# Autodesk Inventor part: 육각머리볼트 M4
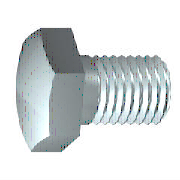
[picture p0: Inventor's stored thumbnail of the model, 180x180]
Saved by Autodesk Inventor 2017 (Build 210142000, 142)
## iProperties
Created: 2012-02
Part Number: 육각머리볼트 M4
Material: 스테인리스강
Description: 6각 머리 나사
Document SubType Name: Modeling
Standard: ISO 4017
Designer: mduedu
Standard Revision: Third edition 1999-08-15
Standards Organization: ISO
Language: ko-KR
Size Designation: M4 x 10
Categories: <MemberInstance><Categories><Category DisplayName="조임쇠" InternalName="e4da775c-781d-43d5-af7c-5136215cf5a6" Mnemonic="FSTN"><Category DisplayName="볼트" InternalN
Density: 8.08 g/cm^3
Appearance: 반광택
IsCustomPart: 0
Author: mduedu
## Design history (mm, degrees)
sketch "스케치1"
  geometry: L1 (0, 3.015)-(0, 2); L2 (1.75, 2)-(10, 2); L3 (10, 2)-(10, 0); L4 (10, 0)-(-0.4, 0); L5 (-2.48, 0)-(12.08, 0) reference; L6 (-0.4, 0)-(-0.4, 3.015); L7 (-0.4, 3.015)-(0, 3.015); L8 (1.75, 2)-(1.32, 2); L9 (1.32, 2)-(0, 2); L10 (0, -0.603)-(0, 3.618) reference
  constraints: 16 end point, 2 collinear, 2 perpendicular, 1 parallel
  dimensions: "d0" = 10 distance between parallel lines of L3 L1 (= NLG); "d1" = 8.25 distance from line of L2.start L3 (= GEL); "d2" = 4 diameter of L2 L4 (= GD); "d9" = 0.4001 distance between parallel lines of L6 L1 (computed from SD); "d10" = 6.03 diameter of L7 L4 (= SD2); "d13" = 0.42952 distance of L2.start L8.end (computed from GAL); "d14" = 4 diameter of L9 L4 (= BDM)
revolve "본체" sketch "스케치1" stored, may be unused: angle "d12" = 90 deg
sketch "스케치2"
  geometry: L1 (0, 4.041)-(3.5, 2.021); L2 (3.5, 2.021)-(3.5, -2.021); L3 (3.5, -2.021)-(0, -4.041); L4 (0, -4.041)-(-3.5, -2.021); L5 (-3.5, -2.021)-(-3.5, 2.021); L6 (-3.5, 2.021)-(0, 4.041); 2 further points
  constraints: 12 end point, 1 coincident, 1 vertical, 11 other
  dimensions: "d11" = 7 distance between parallel lines of L5 L2 (= SW)
extrude "머리" join sketch "스케치2" distance "d3" = 2.4 (= KOH - SD); taper "d4" = 0 deg
sketch "스케치4"
  geometry: L1 (-2.8, 3.5)-(-2.8, 4.041); L2 (-2.8, 4.041)-(-2.487, 4.041); L3 (-2.487, 4.041)-(-2.8, 3.5); L4 (-3.28, 0)-(0.08, 0) reference; L5 (-0.4, 4.041)-(-2.8, 4.041) reference; L6 (-2.8, 2.021)-(-2.8, 4.041) reference
  constraints: 6 end point, 2 collinear, 1 perpendicular, 1 vertical
  dimensions: "d5" = 30 deg angle of L3 L1 (= ANG1); "d19" = 7 diameter of L1.start L4 (= SW0)
revolve "모따기1" sketch "스케치4" stored, may be unused: angle "d21" = 90 deg
workplane "Work Plane1"
body "Solid1"
feature "스레드" dims "d15" = 8.25 (= GEL), "d16" = 0
chamfer "모따기2" distance "d6" = 0.42941 (= -0.5 x SPD + 0.5 x GD); stored, may be unused: second distance "d7" = 0.42952 (computed from GUL), angle "d55" = 45 deg
other parameters: "NLG" = 10 [user parameter; used in 1 equation term], "GD" = 4 (= NND) [user parameter; used in 2 equation terms], "BDM" = 4 (= NND) [user parameter; used in 1 equation term], "KOH" = 2.8 [user parameter; used in 1 equation term], "GEL" = 8.25 [user parameter; used in 2 equation terms], "SW" = 7 [user parameter; used in 2 equation terms], "SW0" = 7 (= SW) [user parameter; used in 1 equation term], "SPD" = 3.14117 (= NND - 1.2269 x PTC) [user parameter; used in 1 equation term], "SD2" = 6.03 [user parameter; used in 2 equation terms], "SD" = 0.4 [user parameter; used in 2 equation terms], "ANG1" = 30 deg [user parameter; used in 1 equation term], "GAL" = 0.42941 (= 0.61345 x PTC) [user parameter; used in 1 equation term], "GUL" = 0.42941 (= 0.61345 x PTC) [user parameter; used in 1 equation term], "d8" = 0, "RR" = 0.2 [user parameter], "d57" = 0, "d58" = 0, "TPU" = 14.28571 (computed from PTC) [user parameter], "GD1" = 3.14117 (= THREADDIA - 1.2269 x PTC) [user parameter], "THREADDIA" = 4 [user parameter; used in 1 equation term], "SDH" = 6.03 (= SD2) [user parameter], "SDHG" = 2.1 [user parameter], "TOA" = 30 deg [user parameter], "PTC" = 0.7 [user parameter; used in 5 equation terms], "NND" = 4 [user parameter; used in 3 equation terms], "E0" = 8.085 [user parameter]
